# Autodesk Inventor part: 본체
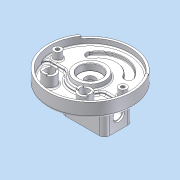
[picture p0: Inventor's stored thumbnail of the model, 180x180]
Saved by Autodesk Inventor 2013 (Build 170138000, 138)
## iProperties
Company: 한국ATC센터
Created: 2015-04
Part Number: 본체
Document SubType Name: Modeling
Designer: KYOUNG IL JANG
Density: 1 g/cm^3
Material: 알루미늄 6061
Mass: 494.771 g
Surface Area: 1387.34 cm^2
Volume: 494.771 cm^3
Author: KYOUNG IL JANG
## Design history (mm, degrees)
sketch "스케치1"
  geometry: L1 (-59, -19)-(-59, 19); L2 (59, 19)-(59, -19); L3 (-41, 19)-(-41, -19); L4 (41, -19)-(41, 19); L5 (38.527, 33.023)-(55.442, 39.179); L6 (-38.527, 33.023)-(-55.442, 39.179); C1 r 90 at (0, 0); C2 r 95 at (0, 0); A1 r 59 centre (0, 19) between (59, 19) and (-59, 19); A2 r 59 centre (0, -19) between (-59, -19) and (59, -19); A3 r 41 centre (0, -19) between (-41, -19) and (41, -19); A4 r 41 centre (0, 19) between (41, 19) and (-41, 19); 2 further points
  constraints: 12 end point, 12 point on circle, 6 centre point, 4 tangent, 2 parallel, 2 point on line, 1 coincident, 1 horizontal alignment, 1 midpoint, 1 vertical, 1 vertical alignment, 3 other
  dimensions: "d2" = 180 diameter of C1; "d3" = 156 dimension on A2 A1; "d4" = 118 distance between parallel lines of L2 L1; "d5" = 18 distance between parallel lines of L2 L4; "d8" = 190 diameter of C2; "d124" = 110 deg dimension on A1.centre point (0, 0) L5.end; "d125" = 140 deg angle of L5 L6
extrude "돌출1" new body sketch "스케치1" distance "d6" = 14; taper "d7" = 0 deg
extrude "돌출2" join sketch "스케치1" distance "d9" = 13; taper "d10" = 0 deg
extrude "돌출3" cut sketch "스케치1" distance "d11" = 7; taper "d12" = 0 deg
sketch "스케치2"
  geometry: C1 r 11.5 at (0, 0); 1 further point
  constraints: 1 centre point, 1 coincident
  dimensions: "d13" = 23 diameter of C1
extrude "돌출4" cut sketch "스케치2" stored distance "d14" = 7; taper "d15" = 0 deg
fillet "모깎기1"
fillet "모깎기2"
sketch "스케치3"
  geometry: L1 (-73.724, 51.622)-(-77.819, 54.49); L2 (73.724, 51.622)-(77.819, 54.49); L3 (0, 0)-(0, -90); A1 r 95 centre (0, 0) between (-77.819, 54.49) and (77.819, 54.49) reference; A2 r 90 centre (0, 0) between (-73.724, 51.622) and (73.724, 51.622) reference; 1 further point
  constraints: 6 end point, 5 point on circle, 1 point on line, 1 vertical, 1 other
  dimensions: "d16" = 250 deg dimension on L2 L1
extrude "돌출5" join sketch "스케치3" distance "d17" = 5; taper "d18" = 0 deg
hole "구멍1" diameter "d21" = 50; stored, may be unused: countersink angle "d25" = 90 deg, drill point angle "d27" = 0 deg; dims "d19" = 10, "d20" = 10, "d22" = 6, "d23" = 4, "d24" = 2, "d26" = 5
fillet "모깎기3" dims "d28" = 0.3
fillet "모깎기5" dims "d30" = 3
sketch "스케치4"
  geometry: C1 r 35 at (0, 0); C2 r 25 at (0, 0); 1 further point
  constraints: 2 centre point, 1 coincident
  dimensions: "d32" = 70 diameter of C1 (derived); "d36" = 10 radial gap between concentric circles of C1 C2
extrude "돌출6" join sketch "스케치4" distance "d33" = 10; taper "d34" = 0 deg
feature "면 기울기2" dims angle "d37" = 10 deg
chamfer "모따기1" distance "d39" = 1; stored, may be unused: second distance "d40" = 2, angle "d41" = 45 deg
fillet "모깎기7" dims "d42" = 5
sketch "스케치5"
  geometry: L1 (-40.249, -12)-(-89.196, -12); L2 (40.249, -12)-(89.196, -12); A1 r 90 centre (0, 0) between (-89.196, -12) and (89.196, -12) reference; A2 r 42 centre (0, 0) between (-40.249, -12) and (40.249, -12); 1 further point
  constraints: 4 end point, 4 point on circle, 1 centre point, 1 collinear, 1 horizontal, 1 point on line
  dimensions: "d43" = 48 radial gap between concentric circles of A1 A2; "d44" = 12 distance from line of point (0, 0) L1
extrude "돌출7" cut sketch "스케치5" stored distance "d45" = 10; taper "d46" = 0 deg
fillet "모깎기8" dims "d47" = 10
chamfer "모따기2" distance "d49" = 1; stored, may be unused: second distance "d50" = 2, angle "d51" = 45 deg
sketch "스케치8"
  geometry: C1 r 9 at (74, 0); C2 r 9 at (-74, 0); A1 r 74 centre (0, 0) between (74, 0) and (-74, 0); 1 further point
  constraints: 3 centre point, 2 horizontal alignment, 2 point on circle, 1 coincident, 1 equal radius
  dimensions: "d64" = 18 diameter of C1; "d65" = 148 diameter of A1
extrude "돌출9" join sketch "스케치8" stored distance "d66" = 5; taper "d67" = 0 deg
sketch "스케치11"
  geometry: C1 r 15 at (40, -52); C2 r 15 at (-40, -52); 1 further point
  constraints: 2 centre point, 1 equal radius, 1 horizontal alignment
  dimensions: "d82" = 52 vertical distance of point (0, 0) C1.centre; "d83" = 30 diameter of C1; "d84" = 80 distance of C2.centre C1.centre; "d85" = 40 horizontal distance of point (0, 0) C1.centre (= 0.5 x d84)
extrude "돌출10" join sketch "스케치11" stored distance "d86" = 10; taper "d87" = 0 deg
node "구멍3"
node "구멍5"
hole "구멍6" diameter "d92" = 20; stored, may be unused: countersink angle "d96" = 90 deg, drill point angle "d98" = 118 deg; dims "d90" = 10, "d91" = 10, "d93" = 6, "d94" = 4, "d95" = 2, "d97" = 8
hole "구멍7" diameter "d101" = 20; stored, may be unused: countersink angle "d105" = 90 deg, drill point angle "d107" = 118 deg; dims "d99" = 10, "d100" = 10, "d102" = 6, "d103" = 4, "d104" = 2, "d106" = 8
fillet "모깎기13" dims "d108" = 3
sketch "스케치13"
  geometry: L1 (-20.252, -58)-(-26, -58); L2 (-42, -58)-(-47.748, -58); L3 (-20.252, -46)-(-26, -46); L4 (-42, -46)-(-47.748, -46); L5 (-108, -65.748)-(-108, -60); L6 (-108, -44)-(-108, -38.252); L7 (-120, -44)-(-120, -38.252); L8 (-120, -60)-(-120, -65.748); A1 r 15 centre (-34, -52) between (-20.252, -58) and (-47.748, -58) reference; A2 r 10 centre (-34, -52) between (-26, -58) and (-42, -58) reference; A3 r 15 centre (-114, -52) between (-108, -65.748) and (-108, -38.252) reference; A4 r 10 centre (-114, -52) between (-108, -60) and (-108, -44) reference; 1 further point
  constraints: 16 end point, 16 point on circle, 3 equal length, 3 point on line, 2 collinear, 1 horizontal, 1 perpendicular
  dimensions: "d114" = 12 distance between parallel lines of L4 L2; "d115" = 6 distance from line of A1.centre L2 (= 0.5 x d114); "d116" = 12 distance between parallel lines of L8 L5 (= d114); "d117" = 6 distance from line of A3.centre L5 (= d115)
extrude "돌출12" join sketch "스케치13" distance "d118" = 3; taper "d119" = 0 deg
fillet "모깎기14" dims "d120" = 1
sketch "스케치14"
  geometry: L1 (23, 32.5)-(-53, 32.5); L2 (-65, 20.5)-(-65, -20.5); L3 (-53, -32.5)-(23, -32.5); L4 (35, -20.5)-(35, 20.5); L5 (30, 20.5)-(30, -20.5); L6 (23, -27.5)-(-53, -27.5); L7 (-60, -20.5)-(-60, 20.5); L8 (-53, 27.5)-(23, 27.5); A1 r 12 centre (-53, -20.5) between (-65, -20.5) and (-53, -32.5); A2 r 12 centre (-53, 20.5) between (-53, 32.5) and (-65, 20.5); A3 r 12 centre (23, 20.5) between (35, 20.5) and (23, 32.5); A4 r 12 centre (23, -20.5) between (23, -32.5) and (35, -20.5); A5 r 7 centre (23, -20.5) between (23, -27.5) and (30, -20.5); A6 r 7 centre (-53, -20.5) between (-60, -20.5) and (-53, -27.5); A7 r 7 centre (-53, 20.5) between (-53, 27.5) and (-60, 20.5); A8 r 7 centre (23, 20.5) between (30, 20.5) and (23, 27.5); A9 r 6 centre (-23, -25) between (-17.546, -27.5) and (-28.454, -27.5); A10 r 6 centre (-23, 25) between (-28.454, 27.5) and (-17.546, 27.5); 6 further points
  constraints: 20 point on circle, 16 end point, 12 point on line, 10 centre point, 8 tangent, 4 equal radius, 4 parallel, 2 perpendicular, 1 horizontal, 1 horizontal alignment, 1 midpoint, 1 vertical alignment, 7 other
  dimensions: "d126" = 35 distance from line of point (0, 0) L4; "d127" = 65 distance of point (35, -32.5) point (35, 32.5); "d128" = 100 distance of point (35, 32.5) point (-65, 32.5); "d132" = 12 radius of A1; "d133" = 5 distance between parallel lines of L5 L4; "d141" = 42 distance from line of A9.centre L2; "d142" = 12 diameter of A9; "d143" = 50 distance of A10.centre A9.centre; "d144" = 25 vertical distance of point (0, 0) A9.centre (= 0.5 x d143)
extrude "돌출13" join sketch "스케치14" distance "d130" = 58; taper "d131" = 0 deg
fillet "모깎기16" dims "d145" = 3
hole "구멍8" diameter "d148" = 4.134; stored, may be unused: countersink angle "d152" = 90 deg, drill point angle "d154" = 118 deg; dims "d146" = 10, "d147" = 10, "d149" = 12, "d150" = 4, "d151" = 2, "d153" = 15
hole "구멍9" diameter "d157" = 4.134; stored, may be unused: countersink angle "d161" = 90 deg, drill point angle "d163" = 118 deg; dims "d155" = 10, "d156" = 10, "d158" = 12, "d159" = 4, "d160" = 2, "d162" = 15
sketch "스케치17"
  geometry: L1 (-58, 110.5)-(-58, -69.5) reference; C1 r 15 at (-29.5, 20.5); 1 further point
  constraints: 1 centre point, 1 horizontal alignment
  dimensions: "d164" = 28.5 distance from line of C1.centre L1; "d165" = 30 diameter of C1
extrude "돌출16" join sketch "스케치17" distance "d166" = 28; taper "d167" = 0 deg
fillet "모깎기17" dims "d168" = 1
hole "구멍10" diameter "d171" = 22; stored, may be unused: countersink angle "d175" = 90 deg, drill point angle "d177" = 118 deg; dims "d169" = 10, "d170" = 10, "d172" = 12, "d173" = 26, "d174" = 4, "d176" = 15
node "솔리드1"
sketch "스케치9"
  geometry: 1 further point
hole "구멍2" sketch "스케치9" diameter "d68" = 8.376; stored, may be unused: countersink angle "d72" = 90 deg, drill point angle "d74" = 120 deg; dims "d69" = 16, "d70" = 4, "d71" = 2, "d73" = 21
sketch "스케치10"
  geometry: 1 further point
hole "구멍4" sketch "스케치10" diameter "d75" = 8.376; stored, may be unused: countersink angle "d79" = 90 deg, drill point angle "d81" = 120 deg; dims "d76" = 16, "d77" = 4, "d78" = 2, "d80" = 21
